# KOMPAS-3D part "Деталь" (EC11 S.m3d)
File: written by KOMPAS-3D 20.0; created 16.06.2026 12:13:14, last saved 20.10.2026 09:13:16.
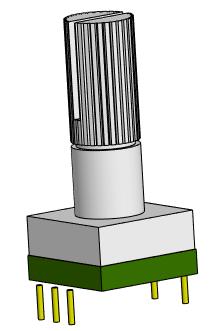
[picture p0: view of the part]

Document properties: Полное имя файла: D:\RicWork\Project-EPS32\box_compas\переключатели и кнопки\EC11 S.m3d

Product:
- Part/product: Деталь
    Материал: Фторопласт-4  ГОСТ 10007-80 Е (density 2200 kg/m3)
    Масса: 0.00354823
  - Body: Тело 3
      Масса: 6.53137e-06
  - Body: Тело 2
      Масса: 0.00353734
  - Body: Тело 4
      Масса: 4.35425e-06

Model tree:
1. Эскиз:10
2. Элемент выдавливания:11
     Расстояние 1 = 2.5
3. Эскиз:12  (with: Элемент выдавливания:11)
4. Элемент выдавливания:13
     Расстояние 1 = 4
5. Эскиз:13  (with: Элемент выдавливания:13)
6. Элемент выдавливания:14
     Расстояние 1 = 7
7. Эскиз:14  (with: Элемент выдавливания:14)
8. Элемент выдавливания:15
     Расстояние 1 = 0.5
9. Эскиз:15  (with: Элемент выдавливания:15)
10. Элемент выдавливания:16
     Расстояние 1 = 12.5
11. Эскиз:17  (with: Элемент выдавливания:16)
12. Элемент выдавливания:18
     Расстояние 2 = 12.5
13. Эскиз:18  (with: Элемент выдавливания:16)
14. Элемент выдавливания:19
     Расстояние 2 = 12.5
15. Массив по концентрической сетке:1  (with: Элемент выдавливания:19, Эскиз:18, Элемент выдавливания:16)  (30 pattern instances)
     Шаг 2 = 360
16. Эскиз:16  (with: Элемент выдавливания:16)
17. Элемент выдавливания:20
     Расстояние 2 = 10
18. Эскиз:19  (with: Элемент выдавливания:11)
19. Элемент выдавливания:21
     Расстояние 1 = 3.5
20. Массив по сетке:2  (with: Элемент выдавливания:21, Эскиз:19)  (3 pattern instances)
     Шаг 1 = 2.5; Угол раствора = 90
21. Эскиз:20  (with: Элемент выдавливания:11)
22. Элемент выдавливания:23
     Расстояние 1 = 3.5
23. Массив по сетке:3  (with: Элемент выдавливания:23, Эскиз:20)  (labels: Фторопласт-4  ГОСТ 10007-80 Е)  (2 pattern instances)
     Шаг 1 = 5; Угол раствора = 90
